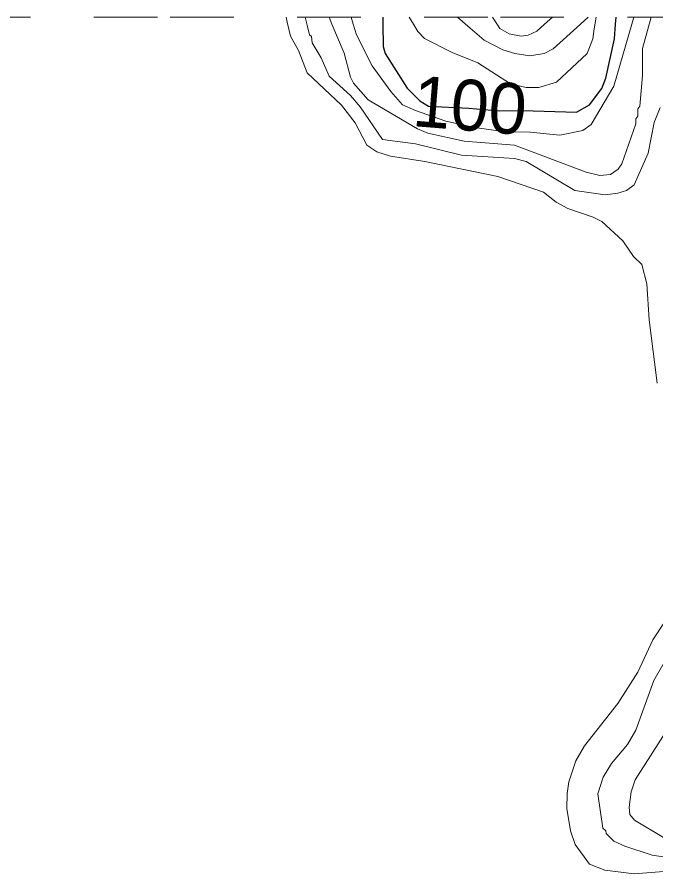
# Model space of a CAD drawing. Extents: x 474.5 to 500, y 7345.7 to 7373.4.
# Drawn here: x 497.159 to 498.165, y 7372.068 to 7373.417 of the extents above; entities that cross this region are included whole.
import ezdxf
from ezdxf.enums import TextEntityAlignment as Align

# ---------------------------------------------------------------- set-up
doc = ezdxf.new("R2010")
doc.units = 0
doc.header["$LTSCALE"] = 0.032
doc.linetypes.add('SHORT_DASHED', pattern=[2.7, 1.5, -1.2])
for name, color, linetype, lineweight in [('1', 7, 'Continuous', 25), ('2', 7, 'Continuous', 13), ('22', 7, 'SHORT_DASHED', 13)]:
    doc.layers.add(name, color=color, linetype=linetype, lineweight=lineweight)
doc.layers.add('61', color=7, linetype='Continuous')

msp = doc.modelspace()

# ---------------------------------------------------------------- linework, layer by layer
at = {"layer": '1'}
msp.add_lwpolyline([(497.7349, 7373.4166), (497.735, 7373.4058), (497.7353, 7373.3704), (497.7387, 7373.3597), (497.7731, 7373.305), (497.7932, 7373.285), (497.8071, 7373.2766), (497.8706, 7373.2735), (497.9187, 7373.2692), (497.9547, 7373.2698), (498.04, 7373.267), (498.0604, 7373.2786), (498.0798, 7373.3042), (498.0863, 7373.3207), (498.0998, 7373.3823), (498.1015, 7373.4058), (498.1023, 7373.4166)], dxfattribs=at)
at = {"layer": '2'}
for points in [[(498.1668, 7372.8407), (498.1542, 7372.9404), (498.1509, 7372.9971), (498.1429, 7373.0274), (498.1295, 7373.0401), (498.113, 7373.0646), (498.0797, 7373.0948), (498.0664, 7373.1017), (498.0263, 7373.1153), (498.0081, 7373.1255), (497.9881, 7373.1409), (497.9161, 7373.1657), (497.8013, 7373.1896), (497.747, 7373.1976), (497.7255, 7373.2045), (497.7101, 7373.2151), (497.6914, 7373.2502), (497.67, 7373.2779), (497.6161, 7373.3288), (497.6025, 7373.364), (497.5896, 7373.3868), (497.5846, 7373.409), (497.5829, 7373.4165)], [(497.6127, 7373.4165), (497.6159, 7373.404), (497.6197, 7373.389), (497.6228, 7373.3863), (497.6237, 7373.3764), (497.6378, 7373.3526), (497.6506, 7373.324), (497.6843, 7373.2931), (497.6995, 7373.2755), (497.7347, 7373.2239), (497.7866, 7373.2175), (497.8587, 7373.1992), (497.9422, 7373.1943), (497.9608, 7373.1896), (498.0371, 7373.1436), (498.0853, 7373.137), (498.1049, 7373.1394), (498.1187, 7373.144), (498.1307, 7373.1527), (498.1526, 7373.2026), (498.1622, 7373.2507), (498.1717, 7373.2744)], [(498.1574, 7373.4166), (498.1532, 7373.4016), (498.1436, 7373.3673), (498.1437, 7373.3246), (498.1397, 7373.2768), (498.1366, 7373.2725), (498.1365, 7373.2608), (498.1334, 7373.2565), (498.1333, 7373.2489), (498.1114, 7373.1856), (498.1058, 7373.1773), (498.0937, 7373.1689), (498.0766, 7373.1673), (498.055, 7373.1724), (497.9422, 7373.215), (497.863, 7373.2213), (497.8061, 7373.2343), (497.7898, 7373.2409), (497.7121, 7373.2867), (497.6887, 7373.3129), (497.6839, 7373.3223), (497.6739, 7373.36), (497.6548, 7373.4058), (497.6503, 7373.4165)], [(497.6852, 7373.4166), (497.6884, 7373.4058), (497.6935, 7373.3889), (497.7184, 7373.3398), (497.7475, 7373.2997), (497.766, 7373.2784), (497.7866, 7373.2695), (497.834, 7373.2528), (497.8798, 7373.2428), (497.9276, 7373.236), (497.9672, 7373.2358), (498.0139, 7373.2311), (498.0498, 7373.238), (498.0628, 7373.2475), (498.0985, 7373.3081), (498.127, 7373.4058), (498.1302, 7373.4166)], [(498.0707, 7373.4166), (498.068, 7373.3984), (498.0656, 7373.3824), (498.0568, 7373.3597), (498.0083, 7373.3145), (497.9805, 7373.3061), (497.9607, 7373.3061), (497.936, 7373.3115), (497.8847, 7373.345), (497.8442, 7373.3612), (497.8006, 7373.383), (497.7903, 7373.394), (497.7832, 7373.4058), (497.7767, 7373.4166)], [(498.0582, 7373.4166), (498.0404, 7373.4005), (498.0032, 7373.3669), (497.9892, 7373.3593), (497.9667, 7373.3556), (497.9428, 7373.3592), (497.924, 7373.3651), (497.8945, 7373.3807), (497.8726, 7373.3994), (497.8525, 7373.4166)], [(497.9076, 7373.4166), (497.9154, 7373.4047), (497.9192, 7373.3989), (497.934, 7373.3902), (497.9529, 7373.3866), (497.964, 7373.3882), (497.9773, 7373.3946), (497.9898, 7373.4058), (498.0019, 7373.4166)], [(498.0378, 7372.114), (498.0306, 7372.1355), (498.0249, 7372.1711), (498.025, 7372.1944), (498.028, 7372.2131), (498.039, 7372.246), (498.0523, 7372.2695), (498.1048, 7372.3362), (498.1365, 7372.3855), (498.1603, 7372.4362), (498.197, 7372.4921)], [(498.2118, 7372.0894), (498.1593, 7372.0974), (498.1159, 7372.1116), (498.0989, 7372.1195), (498.0867, 7372.1315), (498.0861, 7372.1359), (498.0816, 7372.14), (498.0736, 7372.1942), (498.0818, 7372.2201), (498.095, 7372.2418), (498.1203, 7372.2716), (498.1332, 7372.2942), (498.1619, 7372.3724), (498.2, 7372.4391)], [(498.177, 7372.1251), (498.131, 7372.1524), (498.1241, 7372.1612), (498.1231, 7372.1731), (498.1258, 7372.1974), (498.1324, 7372.2161), (498.1844, 7372.2976)], [(498.2175, 7372.0751), (498.1307, 7372.068), (498.0845, 7372.0738), (498.0606, 7372.0833), (498.0378, 7372.114)]]:
    msp.add_lwpolyline(points, dxfattribs=at)
at = {"layer": '22'}
msp.add_lwpolyline([(488.561, 7373.4122), (489.0809, 7373.4126), (489.6009, 7373.413), (490.1208, 7373.4133), (490.6408, 7373.4137), (491.1607, 7373.414), (491.6807, 7373.4143), (492.2006, 7373.4146), (492.7206, 7373.4149), (493.2406, 7373.4151), (493.7605, 7373.4154), (494.2805, 7373.4156), (494.8004, 7373.4158), (495.3204, 7373.416), (495.8403, 7373.4161), (496.3603, 7373.4163), (496.8802, 7373.4164), (497.4002, 7373.4165), (497.9201, 7373.4166), (498.4401, 7373.4166), (498.96, 7373.4167), (499.48, 7373.4167), (500, 7373.4167)], dxfattribs=at)

# ---------------------------------------------------------------- texts
at = {"layer": '61'}
msp.add_text('100', height=0.08, rotation=355.397, dxfattribs=at).set_placement((497.869, 7373.2382), align=Align.CENTER)

doc.saveas('drawing.dxf')
